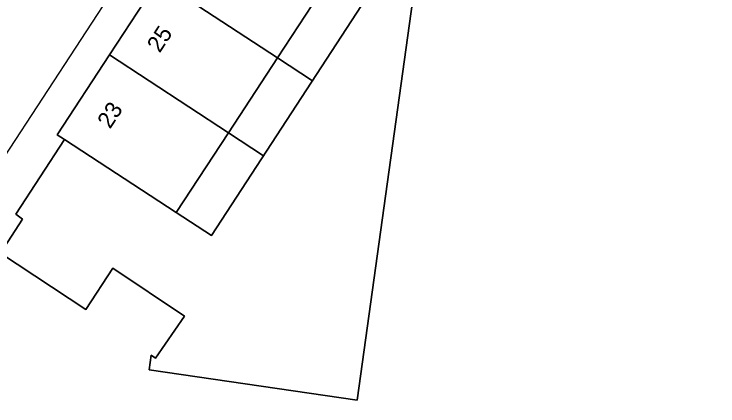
# Model space of a CAD drawing. Extents: x 155640 to 156811, y 382821 to 384049.
# Drawn here: x 156442.83 to 156485.33, y 383696.55 to 383720.18 of the extents above; entities that cross this region are included whole.
import ezdxf

# ---------------------------------------------------------------- set-up
doc = ezdxf.new("R2010")
doc.units = 0
for name, color, linetype in [('IMGEO_Lijnafwatering', 7, 'Continuous'), ('IMGEO_Muur', 7, 'Continuous'), ('IMGEO_Pand', 7, 'Continuous'), ('IMGEO_Pand_nummerreeks', 7, 'Continuous'), ('IMGEO_Pand_overbouw', 7, 'Continuous'), ('IMGEO_Voetgangersgebied_open', 7, 'Continuous'), ('IMGEO_Voetpad_open', 7, 'Continuous')]:
    doc.layers.add(name, color=color, linetype=linetype)

msp = doc.modelspace()

# ---------------------------------------------------------------- linework, layer by layer
at = {"layer": 'IMGEO_Lijnafwatering'}
msp.add_lwpolyline([(156449.169, 383722.207), (156437.575, 383704.494)], dxfattribs=at)
at = {"layer": 'IMGEO_Muur'}
for points in [[(156442.937, 383708.11), (156445.881, 383712.618)], [(156442.019, 383705.761), (156443.341, 383707.811), (156442.937, 383708.11)]]:
    msp.add_lwpolyline(points, dxfattribs=at)
at = {"layer": 'IMGEO_Pand'}
msp.add_lwpolyline([(156526.125, 383742.921), (156504.403, 383768.001), (156496.961, 383761.545), (156495.141, 383758.761), (156489.522, 383750.169), (156483.796, 383750.953), (156467.607, 383726.148), (156463.541, 383696.89), (156450.981, 383698.723), (156451.111, 383699.61), (156451.369, 383699.433), (156453.11, 383701.958), (156448.797, 383704.86), (156447.156, 383702.372), (156442.019, 383705.761), (156438.461, 383700.239), (156438.115, 383699.703), (156438.014, 383699.718), (156436.208, 383686.52)], dxfattribs=at)
for points in [[(156454.503, 383726.765), (156451.542, 383722.239), (156458.727, 383717.547), (156461.689, 383722.072)], [(156451.542, 383722.239), (156448.583, 383717.716), (156455.766, 383713.025), (156458.727, 383717.547)], [(156455.766, 383713.025), (156448.583, 383717.716), (156445.437, 383712.908), (156445.881, 383712.618), (156452.619, 383708.217)]]:
    msp.add_lwpolyline(points, close=True, dxfattribs=at)
at = {"layer": 'IMGEO_Pand_overbouw'}
for points in [[(156461.689, 383722.072), (156458.727, 383717.547), (156460.85, 383716.161), (156463.806, 383720.69)], [(156455.766, 383713.025), (156457.896, 383711.634), (156460.85, 383716.161), (156458.727, 383717.547)], [(156455.766, 383713.025), (156452.619, 383708.217), (156454.756, 383706.822), (156457.896, 383711.634)]]:
    msp.add_lwpolyline(points, close=True, dxfattribs=at)
at = {"layer": 'IMGEO_Voetgangersgebied_open'}
msp.add_lwpolyline([(156430.466, 383687.075), (156432.591, 383702.361), (156438.64, 383701.529), (156438.461, 383700.239), (156442.019, 383705.761), (156443.341, 383707.811), (156442.937, 383708.11), (156445.881, 383712.618), (156445.437, 383712.908), (156448.583, 383717.716), (156451.542, 383722.239), (156454.503, 383726.765), (156457.463, 383731.289), (156460.417, 383735.804), (156463.375, 383740.324), (156466.337, 383744.851), (156469.274, 383749.341)], dxfattribs=at)
at = {"layer": 'IMGEO_Voetpad_open'}
for points in [[(156443.341, 383707.811), (156442.019, 383705.761), (156447.156, 383702.372), (156448.797, 383704.86), (156453.11, 383701.958), (156451.369, 383699.433), (156451.111, 383699.61), (156450.981, 383698.723), (156463.541, 383696.89), (156467.607, 383726.148), (156483.796, 383750.953), (156489.522, 383750.169), (156495.141, 383758.761), (156491.34, 383763.141), (156484.606, 383770.903), (156483.001, 383769.51), (156475.806, 383758.471), (156482.61, 383754.028), (156484.681, 383752.675), (156454.756, 383706.822), (156452.619, 383708.217), (156445.881, 383712.618), (156442.937, 383708.11)], [(156452.619, 383708.217), (156454.756, 383706.822), (156484.681, 383752.675), (156482.61, 383754.028), (156479.445, 383749.193), (156476.467, 383744.644), (156473.528, 383740.155), (156470.565, 383735.629), (156467.606, 383731.11), (156464.65, 383726.595), (156461.689, 383722.072), (156458.727, 383717.547), (156455.766, 383713.025)]]:
    msp.add_lwpolyline(points, close=True, dxfattribs=at)

# ---------------------------------------------------------------- texts
at = {"layer": 'IMGEO_Pand_nummerreeks'}
for s, rotation, p in [('25', 56.8088, (156451.62, 383717.792)), ('23', 56.803, (156448.622, 383713.209))]:
    msp.add_text(s, height=1, rotation=rotation, dxfattribs=at).set_placement(p)

doc.saveas('drawing.dxf')
